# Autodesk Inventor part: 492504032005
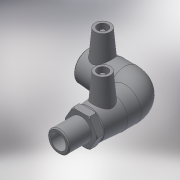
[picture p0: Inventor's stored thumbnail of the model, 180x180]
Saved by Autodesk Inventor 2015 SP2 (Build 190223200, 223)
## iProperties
Created: 2017-06
Part Number: 492504032005
Material: Generic
Description: PLASSON 90° ELBOW MALE TRANSITION 32-1/2"
Document SubType Name: Modeling
Designer: KIM
Mass: 113.899 g
Surface Area: 361.798 cm^2
Volume: 113.899 cm^3
Density: 1 g/cm^3
Appearance: Default
Author: KIM
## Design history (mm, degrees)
derived "492504.ipt"
feature "Solid1::492504.ipt"
tag "TaggingFeature1"
body "Solid1"
other parameters: "d2" = 44, "d4" = 27.66667, "d5" = 39.6, "d8" = 168 deg, "d10" = 16, "d11" = 5.33333, "d29" = 43, "d30" = 15, "d31" = 45.65, "d34" = 5 deg, "d41" = 4, "d42" = 14, "d43" = 0, "d48" = 61, "d49" = 32, "d50" = 27.2, "d51" = 16, "d54" = 90 deg, "d57" = 32, "d59" = 0, "d61" = 90 deg, "d86" = 3, "d87" = 0, "d93" = 0.1, "d94" = 7.25, "d95" = 20.955, "d96" = 14.6685, "d97" = 23, "d98" = 29, "d99" = 44, "d100" = 26.1, "d102" = 1.6, "d106" = 0, "d_" = 32, "L_" = 112, "D_" = 23, "A_" = 43, "d_2" = 12, "L_2" = 29, "D_1" = 44, "R_" = 20.955
